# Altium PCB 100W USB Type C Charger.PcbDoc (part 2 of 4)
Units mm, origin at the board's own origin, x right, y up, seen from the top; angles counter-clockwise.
Board outline 79.45 x 55.68 mm, 4 copper layers (Top Layer, Signal Layer 1, Signal Layer 2, Bottom Layer), stack 1.565 mm thick; 161 components, 84 nets, 462 pads, 2175 vias.
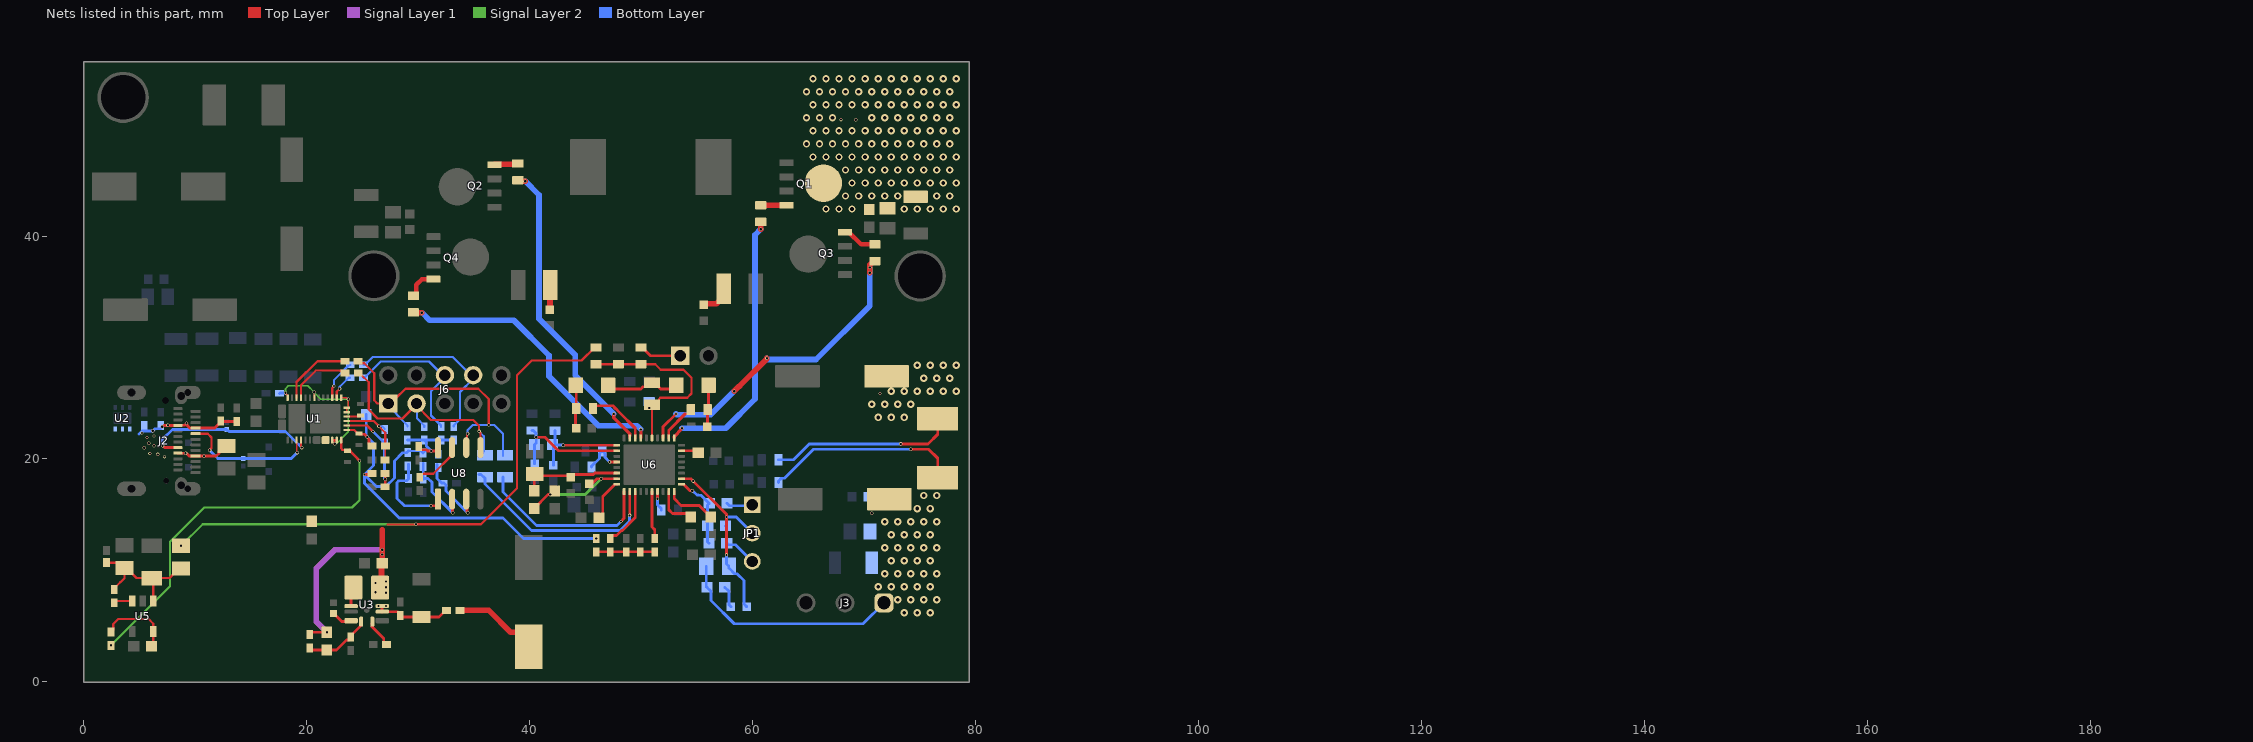
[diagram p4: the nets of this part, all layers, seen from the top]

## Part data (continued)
JP1: library part CMP-0002338-1, "Header, 100mil, 3x1, Tin, TH", Color=Black, Current_A=3A, Manufacturer="Sullins Connector Solutions", Supplier Part Number 1=S1012E-03-ND, Voltage_V=1.8kV
L1: library part CMP-0003375-1, "Ferrite Bead, 21 ohm @ 100 MHz, 6 A, 0805", Manufacturer="Taiyo Yuden", Supplier Part Number 1=587-1765-1-ND, Value1="0.004 ohm", Value2=6A, ValueDisplayed="21 ohm"
L3: library part CMP-0096007-1, "Power Choke Coil 10uH 20% 9A 22mOhm", Manufacturer=Cyntec, Operating Temperature Range="-55°C to +125°C", Test Frequency=100kHz, Tolerance_%=20%
LBL1: library part CMP-0003625-1, "Thermal Transfer Printable Labels, 0.650\" W x 0.200\" H - 10,000 per roll", Manufacturer=Brady, Supplier Part Number 1=97C5133
Logo1: library part CMP-0074838-1, "Texas Instrument Corporate Signature"
Logo3: library part CMP-0074847-1, "FCC_disclaimer"
Q1 Q2 Q3 Q4: library part CMP-0096839-1, "N-Channel 80 V 18.6A (Ta), 70.6A (Tc) 5W (Ta), 71.4W (Tc) Surface Mount PowerPAK® SO-8", Digikey Part Number=742-SIR880BDP-T1-RE3CT-ND, Drain To Source Breakdown Voltage=80V, Input Capacitace At Vds="2930pF @ 40V", Manufacturer=Vishay, Mouser Part Number=78-SIR880BDP-T1-RE3, Operating Temperature Range="-55°C to +150°C", Power_W=5W, Pulse Drain Current=200A, Typ Forward Diode Voltage=0.74V, Value2=SiR122LDP
R1 R6: library part CMP-0026753-1, "RES, 100 k, 1%, 0.063 W, AEC-Q200 Grade 0, 0402", Manufacturer="Stackpole Electronics Inc", Power_W=63mW, Supplier Part Number 1=RMCF0402FT100KCT-ND, TempCo="100 ppm/C", Tolerance_%=1%, Value2=0.063W, Value_Code=100k
R2 R30 R32: library part CMP-0027004-1, "RES, 0, 5%, 0.063 W, 0402", Manufacturer="Yageo America", Power_W=63mW, Supplier Part Number 1=311-0.0JRCT-ND, TempCo="200 ppm/C", Tolerance_%=5%, Value2=0.063W, Value_Code=0000, ValueDisplayed=0
R3 R4 R12 R13: library part CMP-0026918-5, "RES, 3.3 k, 5%, 0.063 W, AEC-Q200 Grade 0, 0402", Manufacturer=Vishay-Dale, Power_W=63mW, Supplier Part Number 1=541-3.3KJCT-ND, TempCo="200 ppm/C", Tolerance_%=5%, Value2=0.063W, Value_Code=3k30, ValueDisplayed=3.3k
R5: library part CMP-0023541-1, "RES, 40.2 k, 0.1%, 0.1 W, 0603", Manufacturer="Susumu Co Ltd", Power_W=100mW, Supplier Part Number 1=RG16P40.2KBCT-ND, TempCo="25 ppm/C", Tolerance_%=0.1%, Value2=0.1W, Value_Code=40k2, ValueDisplayed=40.2k
R7 R14 R15 R22 R23 R24 R74: "RES, 10 k, 5%, 0.063 W, AEC-Q200 Grade 0, 0402", Manufacturer=Vishay-Dale, PartNumber=CRCW040210K0JNED, Power_W=63mW, Supplier Part Number 1=541-10KJCT-ND, TempCo="200 ppm/C", Tolerance_%=5%, Value2=0.063W, Value_Code=10k0, ValueDisplayed=10k
R8 R9 R10 R11 R21 R25 R27 R77: "RES, 0, 5%, 0.063 W, 0402", Manufacturer="Yageo America", PartNumber=RC0402JR-070RL, Power_W=63mW, Supplier Part Number 1=311-0.0JRCT-ND, TempCo="200 ppm/C", Tolerance_%=5%, Value2=0.063W, Value_Code=0000, ValueDisplayed=0
R16 R35 R38 R44 R45 R50 R51 R55 R56 R58 R59 R72: library part CMP-0093629-1, "Thick Film Resistors - SMD 1/10watt ZEROohm Jumper", Manufacturer=Vishay, Operating Temperature Range="-55°C to +155°C", Power=250mW, Power_W=330mW, TempCo=100ppm/°C, Tolerance_%=1%
R17: library part CMP-0026068-2, "RES, 19.6 k, 1%, 0.063 W, 0402", Manufacturer=Vishay-Dale, Power_W=63mW, Supplier Part Number 1=541-19.6KLCT-ND, TempCo="100 ppm/C", Tolerance_%=1%, Value2=0.063W, Value_Code=19k6, ValueDisplayed=19.6k
R18: library part CMP-0026658-1, "RES, 10.0 k, 1%, 0.1 W, 0402", Manufacturer=Panasonic, Power_W=100mW, Supplier Part Number 1=P10.0KLCT-ND, TempCo="100 ppm/C", Tolerance_%=1%, Value2=0.1W, Value_Code=10k0, ValueDisplayed=10.0k
R19: library part CMP-0020817-2, "RES, 3.3, 5%, 0.125 W, 0805", Manufacturer="Yageo America", Power_W=125mW, Supplier Part Number 1=311-3.3ARCT-ND, TempCo="200 ppm/C", Tolerance_%=5%, Value2=0.125W, Value_Code=3R30, ValueDisplayed=3.3
R29 R31: library part CMP-0096841-1, "Res Metal Strip 2512 0.005 Ohm 1% 1W 110ppm/C Molded SMD SMD Embossed Plastic T/R", Digikey Part Number=WSLG-.005CT-ND, Manufacturer=Vishay, Mouser Part Number=71-WSL25125L000FEA, Octopart Part Number=dd8716d1bbbb0240, Operating Temperature Range="-65°C to +170°C", Power_W=1W, TempCo=110ppm/°C, Tolerance_%=1%
R33 R34 R36 R37: library part CMP-0093685-1, "RES Thick Film, 10Ω, 1%, 0.1W, 100ppm/°C, 0603", Approved Alternate Part Number=541-1.00HHCT-ND, Manufacturer=Vishay, Operating Temperature Range="-55°C to +155°C", Power=100mW, TempCo=100ppm/°C, Tolerance_%=1%, Voltage=75V
R39: library part CMP-0024096-3, "RES, 30.1 k, 0.1%, 0.1 W, 0603", Manufacturer="Yageo America", Power_W=100mW, TempCo="25 ppm/C", Tolerance_%=0.1%, Value2=0.1W, Value_Code=30k1, ValueDisplayed=30.1k
R40: library part CMP-0025744-3, "RES, 1.1, 5%, 0.1 W, 0603", Manufacturer=Vishay-Dale, Power_W=100mW, Supplier Part Number 1=541-1.1GCT-ND, TempCo="200 ppm/C", Tolerance_%=5%, Value2=0.1W, Value_Code=1R10, ValueDisplayed=1.1
R41: library part CMP-0018933-2, "Thick Film Resistors - SMD 0805 Anti-Surge Res. 0.1%, 249Kohm", Manufacturer=Panasonic, Power_W=125mW, Supplier Part Number 1=RG20P249KBCT-ND, TempCo="25 ppm/C", Tolerance_%=0.1%, Value2=0.125W, Value_Code=249k
R42 R43: library part CMP-0015022-3, "RES, 3.30, 1%, 0.75 W, AEC-Q200 Grade 0, 1210", Manufacturer=Vishay-Dale, Power_W=750mW, Supplier Part Number 1=541-3.30DCT-ND, TempCo="100 ppm/C", Tolerance_%=1%, Value2=0.75W, Value_Code=3R30, ValueDisplayed=3.30
R46: library part CMP-0021522-3, "Thick Film Resistors - SMD 1/8Watt 1Mohms 1% Commercial Use", Manufacturer="Vishay / Dale", Power_W=125mW, Supplier Part Number 1=P1.00MCCT-ND, TempCo="100 ppm/C", Tolerance_%=1%, Value2=0.125W, Value_Code=1M00, ValueDisplayed=1.00M
R47: library part CMP-0023990-3, "RES, 24.9 k, 0.1%, 0.1 W, 0603", Manufacturer="Yageo America", Power_W=100mW, TempCo="25 ppm/C", Tolerance_%=0.1%, Value2=0.1W, Value_Code=24k9, ValueDisplayed=24.9k
R48: library part CMP-0022977-4, "RES, 294 k, 1%, 0.1 W, 0603", Manufacturer=Yageo, Power_W=100mW, Supplier Part Number 1=311-294KHRCT-ND, TempCo="100 ppm/C", Tolerance_%=1%, Value2=0.1W, Value_Code=294k
R49 R64 R68: library part CMP-0092857-1, "Thick Film Resistors - SMD 1/8watt ZEROohm Jumper", Manufacturer=Vishay, Operating Temperature Range="-55°C to +155°C", Power_W=500mW, TempCo=200ppm/°C, Tolerance_%=5%
R52: library part CMP-0023228-5, "RES, 64.9 k, 1%, 0.1 W, 0603", Manufacturer=Yageo, Power_W=100mW, Supplier Part Number 1=311-64.9KHRCT-ND, TempCo="100 ppm/C", Tolerance_%=1%, Value2=0.1W, Value_Code=64k9, ValueDisplayed=64.9k
R53: library part CMP-0023678-2, "RES, 11.4 k, 0.1%, 0.1 W, 0603", Manufacturer="Yageo America", Power_W=100mW, TempCo="25 ppm/C", Tolerance_%=0.1%, Value2=0.1W, Value_Code=11k4, ValueDisplayed=11.4k
R54: library part CMP-0022990-5, "RES, 2.49 k, 1%, 0.1 W, 0603", Manufacturer=Yageo, Power_W=100mW, Supplier Part Number 1=311-2.49KHRCT-ND, TempCo="100 ppm/C", Tolerance_%=1%, Value2=0.1W, Value_Code=2k49, ValueDisplayed=2.49k
R57: library part CMP-0023199-5, "RES, 5.23 k, 1%, 0.1 W, 0603", Manufacturer=Yageo, Power_W=100mW, Supplier Part Number 1=311-5.23KHRCT-ND, TempCo="100 ppm/C", Tolerance_%=1%, Value2=0.1W, Value_Code=5k23, ValueDisplayed=5.23k
R60: library part CMP-0080485-1, "RES, 10.1 k, 0.1%, 0.1 W, 0603", Manufacturer="TT Electronics/IRC", Power_W=100mW, TempCo="25 ppm/C", Tolerance_%=0.1%, Value2=0.1W, Value_Code=10k1, ValueDisplayed=10.1k
R61: library part CMP-0022371-2, "RES, 3.01 k, 1%, 0.1 W, 0603", Manufacturer=Vishay-Dale, Power_W=100mW, Supplier Part Number 1=541-3.01KHCT-ND, TempCo="100 ppm/C", Tolerance_%=1%, Value2=0.1W, Value_Code=3k01, ValueDisplayed=3.01k
R62: library part CMP-0023018-5, "RES, 30.1 k, 1%, 0.1 W, 0603", Manufacturer=Yageo, Power_W=100mW, Supplier Part Number 1=311-30.1KHRCT-ND, TempCo="100 ppm/C", Tolerance_%=1%, Value2=0.1W, Value_Code=30k1, ValueDisplayed=30.1k
R63: library part CMP-0022735-5, "RES, 100 k, 1%, 0.1 W, 0603", Manufacturer=Yageo, Power_W=100mW, Supplier Part Number 1=311-100KHRCT-ND, TempCo="100 ppm/C", Tolerance_%=1%, Value2=0.1W, Value_Code=100k
R67: library part CMP-0026133-2, "RES, 1.10, 1%, 0.063 W, AEC-Q200 Grade 0, 0402", Manufacturer=Vishay-Dale, Power_W=63mW, Supplier Part Number 1=541-1.10LLCT-ND, TempCo="100 ppm/C", Tolerance_%=1%, Value2=0.063W, Value_Code=1R10, ValueDisplayed=1.10
R69 R70 R71 R73: library part CMP-0078781-1, "RES, 10.5 k, 1%, 0.063 W, 0402", Manufacturer="Yageo America", Power_W=63mW, Supplier Part Number 1=YAG2951CT-ND, TempCo="100 ppm/C", Tolerance_%=1%, Value2=0.063W, Value_Code=10k5, ValueDisplayed=10.5k
R75: library part CMP-0018483-2, "RES, 7.50 k, 1%, 0.25 W, 1206", Manufacturer="Yageo America", Power_W=250mW, Supplier Part Number 1=311-7.50KFRCT-ND, TempCo="100 ppm/C", Tolerance_%=1%, Value2=0.25W, Value_Code=7k50, ValueDisplayed=7.50k
U1: library part CMP-0098263-1, "USB Type-C and USB PD Controller with Integrated Power Switches Optimized for Power Applications", Manufacturer="Texas Instruments", Operating Temperature Range=to
U2: library part CMP-0077834-1, "22-V Precision Surge Protection Clamp, DRV0006A (WSON-6)", Alternate Manufacturer="Texas Instruments"
U3: library part CMP-0097147-1, "3-V to 65-V Input, 1-V to 13-V Output, 600-mA Synchronous Buck Converter Power Module in a HotRod QFN Package", Manufacturer="Texas Instruments", Max Supply Voltage=65V, Min Supply Voltage=3.6V, Nominal Supply Current=17-18uA, Operating Temperature Range="-40°C to +125°C", Output Voltage=1-13V, Switching Frequency=200-2200kHz
U5: library part CMP-0035539-1, "Single Output LDO, 150 mA, Fixed 3.3 V Output, 2.7 to 10 V Input, with Low IQ, 5-pin SOT-23 (DBV), -40 to 125 degC, Green (RoHS & no Sb/Br)", Manufacturer="Texas Instruments"
U6: library part CMP-0093460-1, Alternate Manufacturer=None, Manufacturer="Texas Instruments", Operating Temperature Range=to
U8: library part CMP-0091847-1, "EEPROM Memory IC 512Kb (64K x 8) I²C 1MHz 900ns 8-SOIC", Digikey Part Number=CAT24C512WI-GT3OSCT-ND, Frequency_Fixed=1MHz, Manufacturer="ON Semi", Max Supply Voltage=5.5V, Min Supply Voltage=1.8V, Mouser Part Number=863-CAT24C512WI-GT3, Operating Temperature Range="-40°C to +85°C"
ZZ1: library part CMP-0003616-3
ZZ2: library part CMP-0077236-1
ZZ3: library part CMP-0077237-1
ZZ4: library part CMP-0077238-1

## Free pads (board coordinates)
  round 4.6 hole 4: 2(3.538,52.436) 2(26.037,36.44) 2(75.041,36.42)

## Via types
v1: diameter 0.4, hole 0.2, Top Layer to Bottom Layer, 1357 vias
v2: diameter 0.66, hole 0.33, Top Layer to Bottom Layer, 627 vias
v3: diameter 0.3, hole 0.2, Top Layer to Bottom Layer, tented both sides, 152 vias
v4: diameter 0.5, hole 0.2, Top Layer to Bottom Layer, 18 vias
v5: diameter 0.5, hole 0.2, Top Layer to Bottom Layer, tented both sides, 16 vias
v6: diameter 0.4, hole 0.2, Top Layer to Bottom Layer, tented both sides, 3 vias
v7: diameter 0.35, hole 0.2, Top Layer to Bottom Layer, tented both sides, 2 vias

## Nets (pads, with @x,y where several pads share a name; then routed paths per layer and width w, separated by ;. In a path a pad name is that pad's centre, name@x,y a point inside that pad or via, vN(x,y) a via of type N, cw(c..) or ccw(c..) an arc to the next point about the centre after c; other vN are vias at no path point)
/CE: R58.1 U6.7 | length 1.8
  Top Layer w0.254: v3(51.481,16.428) U6.7@51.481,17.083
  Bottom Layer w0.254: v3@51.481,16.415 51.481,15.877 51.81,15.548 R58.1@51.81,15.423
/INT: R73.1 U6.3 | length 5.4
  Top Layer w0.254: R73.1@47.234,12.867 47.234,12.967 47.407,13.14 47.792,13.14 48.246,13.594 48.341,13.594 49.481,14.735 U6.3@49.481,17.083
/PG: R69.1 U6.6 | length 4.3
  Top Layer w0.254: U6.6@50.981,17.083 50.981,13.896 51.23,13.648 51.23,12.868 R69.1@51.231,12.867
ACN: C27.2 C31.1 R34.1 U6.29 | length 8.8
  Top Layer w0.254: v3(43.016,21.23) 43.019,21.233 U6.29@47.831,21.233
  Bottom Layer w0.254: C31.1@42.14,19.435 42.14,21.183 42.147,21.19 42.153,21.196 C27.2@42.216,21.259 ; R34.1@42.282,22.548 42.282,21.325 C27.2@42.216,21.259 ; v3(43.016,21.23) 43.003,21.23 42.985,21.249 42.227,21.249 C27.2@42.216,21.259
ACOV: C40.1 R48.1 R52.2 U6.35 | length 10.4
  Top Layer w0.254: R48.1@40.423,15.548 40.423,15.573 41.65,16.799 41.865,16.799 41.872,16.793 41.872,16.801 R52.2@41.878,16.808 ; v3(41.857,16.808) R52.2@41.878,16.808 ; R52.2@42.254,17.132 41.93,16.808 R52.2@41.878,16.808 ; C40.1@45.365,17.781 45.391,17.755 45.591,17.755 46.068,18.233 v3(46.423,18.233) U6.35@47.831,18.233 U6.35@47.829,18.231
  Signal Layer 2 w0.254: v3(41.857,16.808) 44.997,16.808 v3(46.423,18.233)
ACP: C27.1 C30.1 R33.1 U6.30 | length 11
  Top Layer w0.254: v3@40.608,21.95 41.38,21.95 42.597,20.733 U6.30@47.831,20.733
  Bottom Layer w0.254: R33.1@40.207,22.561 40.332,22.561 40.58,22.313 40.58,22.161 40.587,22.154 40.587,21.959 v3(40.596,21.95) 40.596,21.442 C27.1@40.452,21.298 C30.1@40.452,19.579
ACUV: C37.1 R46.1 R48.2 U6.34 | length 8.9
  Top Layer w0.254: R48.2@40.423,17.148 40.423,18.292 40.631,18.5 43.528,18.5 C37.1@43.671,18.357 43.925,18.611 45.731,18.611 45.853,18.733 U6.34@47.831,18.733
ADCIN1: R6.2 R25.2 R30.2 U1.2 | length 8.5
  Top Layer w0.2: U1.2@23.594,22.999 25.416,22.999 v3(25.949,22.467) ; R30.2@27.043,17.505 R6.2@27.044,18.692
  Bottom Layer w0.254: v3(25.949,22.467) 26.662,21.754 26.666,21.754 26.994,21.426 26.994,18.248 27.043,18.199 v3(27.043,18.187)
ADCIN2: R1.1 R2.2 R25.1 U1.3 | length 7
  Top Layer w0.152: R2.2@27.044,19.912 R1.1@27.044,21.147
  Top Layer w0.2: U1.3@23.594,23.399 26.009,23.399 27.043,22.365 27.043,21.176 R1.1@27.059,21.16
  Bottom Layer w0.152: v3(26.48,22.928) 26.77,22.928 26.994,22.704 R25.1@26.994,22.627
BAT: C61.1 C62.1 C67.2 C68.1 C69.1 J3.1 R29.2 R37.1 R40.2 R41.2 R77.2 | length 45.8
  Top Layer w0.254: v3(74.188,20.878) 75.796,20.878 76.611,20.063 R29.2@76.611,18.326
  Top Layer w0.5: R77.2@33.756,6.41 36.341,6.41 38.295,4.455 38.929,4.455 39.929,3.455 C62.1@39.929,3.163
  Bottom Layer w0.254: R41.2@55.843,10.381 55.843,8.54 R40.2@55.906,8.476 55.931,8.476 56.279,8.128 56.279,7.297 58.364,5.212 69.919,5.212 J3.1@71.799,7.092 ; R37.1@62.333,17.899 62.333,18.024 62.581,18.272 62.876,18.272 65.482,20.878 v3(74.188,20.878)
  other v2: 73.604,6.203 74.773,6.203 75.941,6.203 73.02,7.371 74.188,7.371 75.357,7.371 76.525,7.371 71.267,8.539 72.436,8.539 73.604,8.539 74.773,8.539 75.941,8.539 71.852,9.708 73.02,9.708 74.188,9.708 75.357,9.708 76.525,9.708 72.436,10.876 73.604,10.876 74.773,10.876 75.941,10.876 71.852,12.045 73.02,12.045 74.188,12.045 75.357,12.045 76.525,12.045 72.436,13.213 73.604,13.213 74.773,13.213 75.941,13.213 71.852,14.381 73.02,14.381 74.188,14.381 75.357,14.381 76.525,14.381 74.773,15.55 75.941,15.55 75.357,16.718 76.525,16.718
  other v3: 70.688,15.141
BTST1: R50.1 U6.26 | length 5.9
  Top Layer w0.254: R50.1@45.534,24.346 45.534,24.471 45.782,24.719 45.907,24.719 45.971,24.783 47.455,24.783 47.732,24.506 47.742,24.506 48.022,24.227 48.022,24.216 49.481,22.756 U6.26@49.481,21.883
BTST2: R51.1 U6.20 | length 3.5
  Top Layer w0.254: U6.20@52.481,21.883 52.481,22.569 53.964,24.052 54.22,24.052 54.468,24.3 R51.1@54.468,24.425
C_CC1: C11.1 J2.A5 U1.28 | length 12.3
  Top Layer w0.152: U1.28@19.094,21.699 19.118,21.675 19.118,20.644 19.149,20.613 v3(19.149,20.573)
  Top Layer w0.2: J2.A5@10.043,22.267 11.119,22.267 11.46,21.926 11.46,20.977 11.293,20.81 v3(11.293,20.782)
  Bottom Layer w0.254: v3(11.293,20.782) 12.031,20.044 C11.1@14.315,20.044 18.621,20.044 v3(19.149,20.573)
C_CC2: C10.1 J2.B5 U1.29 | length 16.2
  Top Layer w0.152: U1.29@19.494,21.699 19.494,21.12 19.556,21.058 v3(19.556,21.018) ; U1.29@19.505,21.699 U1.29@19.505,21.729
  Top Layer w0.254: v3(7.077,21.175) 7.09,21.175 7.248,21.017 J2.B5@8.443,21.017
  Bottom Layer w0.254: v3(7.077,21.175) 7.077,21.775 7.961,22.659 11.637,22.659 11.64,22.656 C10.1@12.693,22.656 ; C10.1@12.819,22.638 12.819,22.618 12.902,22.535 12.977,22.535 13.051,22.461 18.113,22.461 18.861,21.714 v3(19.556,21.018)
DRV_SUP: C42.1 R16.1 R49.2 R55.2 R72.2 U6.23 | length 18.1
  Top Layer w0.2: R72.2@45.961,28.507 R55.2@47.963,28.507 R16.1@49.981,28.507 51.272,28.507 51.771,28.009 53.814,28.009 54.535,27.287 54.535,25.877 54.145,25.487 51.723,25.487 51.606,25.37 51.606,25.25 51.231,24.875 R49.2@50.981,24.875 U6.23@50.981,21.883 ; v3(50.726,24.576) 50.731,24.581 R49.2@50.731,24.849
  Bottom Layer w0.2: v3(50.726,24.576) 50.726,24.894 C42.1@50.731,24.899
EXT_DRV: J4.1 R16.2 | length 4.5
  Top Layer w0.254: R16.2@49.981,30.007 50.106,30.007 50.856,29.257 J4.1@53.512,29.257
  Bottom Layer w0.254: J4.1@53.081,29.689 J4.1@53.512,29.257
FB: C34.2 JP1.2 R41.1 R47.2 U6.12 | length 18.3
  Top Layer w0.254: U6.12@53.631,18.233 54.457,18.233 54.566,18.125 v3(54.674,18.016) ; v3(54.674,18.016) 57.653,15.037 57.653,14.801 v3(57.662,14.792) v3(57.662,11.395)
  Bottom Layer w0.254: R47.2@57.587,13.996 57.662,14.071 v3(57.662,14.792) 58.536,14.792 JP1.2@59.981,13.348 ; v3(57.662,11.395) 57.662,10.594 R41.1@57.875,10.381 57.875,10.216 58.383,9.708 58.616,9.708 59.225,9.099 59.225,6.998 C34.2@59.479,6.744
FBG: R39.1 R47.1 R53.1 U6.11 | length 6.9
  Top Layer w0.254: U6.11@53.631,17.733 53.802,17.733 54.381,17.155 54.594,17.155 v3(54.602,17.146)
  Bottom Layer w0.254: v3(54.602,17.146) 54.611,17.137 54.637,17.137 55.006,16.768 55.135,16.768 55.153,16.75 55.374,16.75 56.027,16.097 56.098,16.026 R39.1@56.123,16.026 55.957,15.86 R47.1@55.957,13.996 ; R47.1@55.987,13.996 R47.1@55.957,13.996 ; R53.1@56.091,12.433 55.957,12.567 R47.1@55.957,13.996
FSW_SYNC: R63.2 U6.36 | length 3.8
  Top Layer w0.254: R63.2@46.217,14.745 R63.2@46.217,14.745 46.567,15.093 46.567,16.64 47.66,17.733 U6.36@47.831,17.733
HIDRV1: R38.2 U6.27 | length 27.6
  Top Layer w0.254: U6.27@48.979,22.064 48.979,21.885 U6.27@48.981,21.883
  Top Layer w0.3: v3(47.545,24.029) 47.545,23.71 48.979,22.276 U6.27@48.979,22.064
  Top Layer w0.508: R38.2@38.942,45.012 39.029,44.925 v3(39.616,44.925)
  Bottom Layer w0.508: v3(39.616,44.925) 40.843,43.698 40.843,32.582 44.09,29.336 44.09,27.484 v3(47.545,24.029)
HIDRV2: R35.2 U6.19 | length 24.9
  Top Layer w0.3: U6.19@52.981,21.883 52.981,22.008 53.672,22.698 v3(53.672,22.757)
  Top Layer w0.5: v3(60.738,40.619) R35.2@60.739,41.267
  Bottom Layer w0.508: v3(53.672,22.757) 57.592,22.757 60.222,25.388 60.222,40.103 v3(60.738,40.619)
I2C_SCL: J6.1 R10.2 R12.2 R68.2 U8.6 | length 28.6
  Top Layer w0.2: R10.2@24.623,28.778 24.808,28.593 25.163,28.593 26.055,27.702 26.055,25.268 26.339,24.983 27.116,24.983 27.263,24.836 J6.1@27.914,25.487 ; J6.1@27.976,25.426 28.858,26.307 35.406,26.307 36.33,25.383 v3(36.33,23.054) ; U8.6@34.317,20.362 34.383,20.428 34.383,22.172 34.438,22.227 v3(34.438,22.254)
  Bottom Layer w0.2: J6.1@27.325,24.774 28.05,24.049 28.05,24.001 29.036,23.014 R12.2@29.036,22.914 ; v3(34.438,22.254) 34.438,22.589 34.903,23.054 v3(36.33,23.054) 36.832,23.054 37.619,22.266 R68.2@37.619,20.276
I2C_SDA: J6.3 R11.2 R13.2 R64.2 U8.5 | length 21.4
  Top Layer w0.2: R11.2@24.629,27.719 24.729,27.719 24.929,27.519 25.564,26.885 25.564,24.429 26.356,23.637 28.604,23.637 J6.3@29.729,24.762 ; J6.3@29.865,24.774 31.135,23.504 34.953,23.504 35.469,22.988 35.469,22.45 35.587,22.331 U8.5@35.587,21.027
  Bottom Layer w0.2: J6.3@29.865,24.774 29.896,24.743 29.896,23.649 30.555,22.991 R13.2@30.555,22.891 ; v3(35.469,22.477) 35.896,22.05 35.896,20.703 35.758,20.565 R64.2@35.705,20.565
I2CS_SCL: J6.8 R3.1 R8.2 | length 16
  Bottom Layer w0.2: R8.2@25.108,28.44 25.208,28.44 25.907,29.139 33.12,29.139 34.945,27.314 34.945,27.189 33.756,26 33.756,23.561 33.197,23.003 R3.1@33.197,22.903
I2CS_SDA: J6.6 R4.1 R9.2 | length 13.8
  Bottom Layer w0.2: R9.2@25.095,27.296 25.195,27.296 26.638,28.739 30.98,28.739 32.405,27.314 31.158,26.067 31.158,23.901 32.061,22.998 R4.1@32.061,22.898
ICHG: R60.2 U6.9 | length 3.9
  Top Layer w0.254: U6.9@52.481,17.083 52.481,15.448 52.833,15.096 54.153,15.096 R60.2@54.453,14.796
ILIM_HIZ: R54.2 U6.10 | length 4.6
  Top Layer w0.254: U6.10@52.981,17.083 52.981,16.444 53.586,15.84 55.218,15.84 56.237,14.821 R54.2@56.237,14.796
LDO_1V5: C9.2 U1.4 | length 1.2
  Top Layer w0.2: U1.4@23.594,23.799 24.755,23.799 C9.2@24.813,23.857
LDO_3V3: C7.2 C8.2 C15.1 R1.2 R3.2 R4.2 R6.1 R7.2 R12.1 R13.1 R14.2 R15.2 R67.1 U1.1 U8.8 | length 50.2
  Top Layer w0.2: U1.1@23.794,22.599 24.266,22.599 24.584,22.281 C8.2@24.698,22.281
  Top Layer w0.254: C8.2@24.698,22.281 24.762,22.217 25.174,22.217 25.586,21.806 25.586,21.333 25.759,21.16 R1.2@25.859,21.16 ; v3(25.193,18.611) 25.202,18.62 25.771,18.62 R6.1@25.844,18.692 ; C15.1@30.064,21.104 30.064,21.004 30.237,20.831 30.745,20.831 30.855,20.722 31.176,20.722 v3(31.184,20.713) 31.643,20.713 31.777,20.847 U8.8@31.777,21.027
  Bottom Layer w0.2: R7.2@29.139,20.731 29.157,20.713 30.25,20.713 R14.2@30.441,20.522 30.632,20.713 v3(31.184,20.713) R15.2@31.698,20.713
  Bottom Layer w0.254: v3@25.181,18.611 25.187,18.605 25.38,18.412 25.38,18.405 26.262,17.523 27.101,17.523 27.878,18.3 27.878,19.827 28.606,20.556 28.966,20.556 29.139,20.729 R7.2@29.139,20.731 ; C7.2@25.34,23.983 25.34,22.091 25.444,21.987 25.444,21.963 25.998,21.409 25.998,19.415 v3(25.193,18.611) 25.185,18.602 25.185,18.344 25.174,18.334 25.174,17.824 28.3,14.698 37.623,14.698 39.454,12.867 v3(45.971,12.867) ; R12.1@29.036,21.714 30.531,21.714 R13.1@30.555,21.691 ; v3(31.184,20.713) 30.728,21.169 30.728,21.518 R13.1@30.555,21.691 ; R3.2@33.197,21.703 33.185,21.691 32.061,21.691 R13.1@30.555,21.691
  other v3: 25.444,21.975
LODRV1: R44.1 U6.25 | length 26.6
  Top Layer w0.254: U6.25@49.981,21.883 v3(49.981,22.654)
  Top Layer w0.508: R44.1@29.582,33.153 29.608,33.127 v3(30.333,33.127)
  Bottom Layer w0.5: 46.155,22.998 49.638,22.998 v3(49.981,22.654)
  Bottom Layer w0.508: v3(30.333,33.127) 31.016,32.443 38.585,32.443 41.737,29.292 41.737,27.416 46.155,22.998
LODRV2: R45.1 U6.21 | length 29
  Top Layer w0.254: U6.21@51.981,21.883 51.981,22.887 v3(53.131,24.037)
  Top Layer w0.5: v3(70.513,36.709) v3(70.513,37.174)
  Top Layer w0.508: v3(58.354,26.08) 58.813,26.539 58.841,26.539 61.29,28.988 v3(61.29,29.029) ; v3(70.513,37.174) 70.513,37.414 70.85,37.752 R45.1@70.975,37.752
  Bottom Layer w0.508: v3(53.131,24.037) 53.201,23.967 56.244,23.967 58.354,26.078 v3(58.354,26.08) ; v3(61.29,29.029) 61.4,28.919 65.697,28.919 70.513,33.735 v3(70.513,36.709) v3(70.513,37.174)
MODE: R61.2 U6.17 | length 1.6
  Top Layer w0.254: U6.17@53.631,20.733 54.944,20.733 R61.2@55.136,20.541
NetC3_1: C3.1 C4.1 C5.1 C6.1 J2.A4 J2.A9 J2.B4 J2.B9 L1.1 U2.4 U2.5 U2.6 | length 14.7
  Top Layer w0.254: v3(7.045,22.887) 7.058,22.887 7.188,23.017 v3(7.55,23.017) J2.B9@8.443,23.017 8.451,23.025 9.041,23.025 9.212,23.197 v3(9.224,23.197) 9.224,23.184 9.266,23.142 9.266,23.026 9.517,22.775 10.035,22.775 J2.A4@10.043,22.767 11.758,22.767 12.285,23.295 C5.1@12.285,23.395 12.32,23.36 C6.1@13.733,23.36 ; J2.B4@8.443,20.517 8.448,20.513 9.137,20.513 9.15,20.499 9.242,20.499 9.466,20.275 10.035,20.275 10.05,20.261 10.783,20.261 v3(10.789,20.255) 10.79,20.256 11.876,20.256 12.125,20.505 12.125,20.67 12.633,21.178 L1.1@12.799,21.178
  Bottom Layer w0.254: 4.952,22.233 5.243,22.524 6.206,22.524 6.401,22.718 6.876,22.718 v3(7.045,22.887)
  other v3: 7.246,20.212 6.637,20.413 5.935,20.493 9.141,20.508 5.428,21.007 6.301,21.19 5.837,21.414 5.68,21.93 6.301,22.067 5.219,22.329 6.194,22.524
NetC16_1: C16.1 C17.1 R77.1 U3.2 U3.3 | length 6.8
  Top Layer w0.254: U3.2@26.772,6.284 U3.2@26.79,6.302 ; 26.772,6.622 26.772,6.32 U3.2@26.79,6.302 ; C17.1@28.241,6.122 C17.1@28.387,5.976 ; R77.1@32.556,6.41 32.456,6.41 31.865,5.818 C16.1@30.289,5.818 28.545,5.818 C17.1@28.387,5.976 ; U3.2@26.79,6.302 28.162,6.302 28.387,6.076 C17.1@28.387,5.976
  other v7: 26.44,6.802 27.12,6.802
NetC18_1: C18.1 U3.8 | length 1.9
  Top Layer w0.254: C18.1@22.404,6.142 22.429,6.142 23.151,5.421 23.921,5.421 U3.8@23.99,5.49
NetC19_2: C19.2 R5.1 R18.2 U3.9 | length 5.8
  Top Layer w0.254: C19.2@20.288,3.051 20.288,3.03 20.461,2.857 22.675,2.857 23.564,3.747 23.771,3.747 23.944,3.92 R18.2@23.944,4.02 ; R18.2@23.944,4.12 24.842,5.017 24.842,5.192 U3.9@24.872,5.222
NetC24_1: C24.1 D3.1 R19.1 R27.2 R75.1 U5.1 | length 12.1
  Top Layer w0.2: D3.1@2.04,10.699 3.025,10.699 3.491,10.233 C24.1@3.656,10.233 ; R27.2@2.725,8.298 2.725,8.398 3.276,8.948 3.306,8.948 3.656,9.298 C24.1@3.656,10.233 ; U5.1@6.241,7.264 6.241,9.165 R75.1@6.091,9.315 ; R19.1@8.724,10.184 8.559,10.184 7.69,9.315 R75.1@6.091,9.315 ; C24.1@3.656,10.233 3.821,10.233 4.739,9.315 R75.1@6.091,9.315
NetC25_1: C25.1 R21.2 U5.5 | length 6.8
  Top Layer w0.2: R21.2@2.454,4.481 2.654,4.681 2.654,5.201 3.092,5.639 5.826,5.639 6.241,5.225 6.241,3.366 C25.1@6.091,3.216
NetC34_1: C34.1 R40.1 | length 2
  Bottom Layer w0.254: R40.1@57.506,8.476 57.531,8.476 57.879,8.128 57.879,6.921 C34.1@58.057,6.744
NetC35_1: C35.1 R42.1 | length 3.2
  Top Layer w0.508: R42.1@41.558,36.462 41.558,35.762 R42.1@41.793,35.527 ; C35.1@41.813,33.41 41.838,33.435 41.838,35.572 R42.1@41.863,35.597
NetC36_1: C36.1 R43.1 | length 2.8
  Top Layer w0.508: C36.1@55.623,33.827 55.727,33.931 56.766,33.931 57.403,34.568 R43.1@57.403,35.268
NetC38_2: C38.2 D4.1 R50.2 | length 3.7
  Top Layer w0.254: R50.2@44.127,24.346 44.127,22.815 C38.2@44.166,22.776 ; D4.1@44.138,26.612 44.183,26.567 R50.2@44.183,24.517
NetC39_1: C39.1 D5.1 R51.2 | length 3.8
  Top Layer w0.254: C39.1@55.929,22.886 55.968,22.925 R51.2@55.968,24.425 56.052,24.51 D5.1@56.052,26.612
NetD4_2: D4.2 D5.2 R49.1 | length 6.8
  Top Layer w0.254: D4.2@47.038,26.612 47.365,26.285 49.998,26.285 50.189,26.477 50.883,26.477 51.231,26.825 51.771,26.285 52.825,26.285 D5.2@53.152,26.612
NetJP1_1: JP1.1 R39.2 | length 2.4
  Bottom Layer w0.254: R39.2@57.723,16.026 57.948,15.801 59.894,15.801 JP1.1@59.981,15.888
NetJP1_3: JP1.3 R53.2 | length 3
  Bottom Layer w0.254: R53.2@57.691,12.433 57.813,12.311 58.477,12.311 JP1.3@59.981,10.808
NetQ1_4: Q1.4 R35.1 | length 2.3
  Top Layer w0.508: R35.1@60.739,42.767 Q1.4@63.05,42.767
NetQ2_4: Q2.4 R38.1 | length 2.2
  Top Layer w0.508: Q2.4@36.838,46.397 36.888,46.448 38.878,46.448 R38.1@38.942,46.512
NetQ3_4: Q3.4 R45.2 | length 3.1
  Top Layer w0.4: Q3.4@68.638,40.349 69.736,39.252 R45.2@70.975,39.252
  Top Layer w0.508: Q3.4@68.308,40.349 Q3.4@68.638,40.349
NetQ4_4: Q4.4 R44.2 | length 2.6
  Top Layer w0.4: R44.2@29.582,34.653 29.658,34.653 29.833,34.828 29.833,35.628 30.343,36.138 Q4.4@31.063,36.138
NetR7_1: R7.1 R23.2 U8.1 | length 8.4
  Top Layer w0.254: v3(31.158,15.801) 31.632,15.801 31.777,15.946 U8.1@31.777,16.395
  Bottom Layer w0.254: R7.1@29.139,19.531 R23.2@29.139,18.247 29.139,18.215 28.966,18.042 28.262,18.042 28.114,17.894 28.114,16.457 28.77,15.801 v3(31.158,15.801)
NetR8_1: R8.1 U1.9 | length 3.7
  Top Layer w0.2: U1.9@22.294,25.499 22.294,26.376 22.442,26.523 v3(22.442,26.55)
  Bottom Layer w0.2: v3(22.442,26.55) 22.442,27.074 23.808,28.44 R8.1@23.908,28.44
NetR9_1: R9.1 U1.8 | length 2.4
  Top Layer w0.2: U1.8@22.694,25.499 22.694,26.045 v3(22.956,26.307)
  Bottom Layer w0.2: v3(22.956,26.307) 22.975,26.326 22.975,26.477 23.595,27.096 23.795,27.296 R9.1@23.895,27.296
NetR10_1: R10.1 U1.17 | length 6.3
  Top Layer w0.2: U1.17@19.094,25.499 19.094,26.907 20.965,28.778 R10.1@23.247,28.778
NetR11_1: R11.1 U1.16 | length 5.7
  Top Layer w0.2: U1.16@19.494,25.499 19.494,26.61 20.812,27.927 23.012,27.927 23.02,27.919 23.229,27.919 R11.1@23.429,27.719
NetR14_1: R14.1 R24.2 U8.2 | length 7.1
  Top Layer w0.254: U8.2@33.047,16.395 33.095,16.347 33.095,15.184 v3(33.104,15.175)
  Bottom Layer w0.254: R14.1@30.453,19.598 R24.2@30.453,18.182 30.529,18.258 30.884,18.258 31.232,17.91 31.232,17.046 v3(33.104,15.175)
NetR15_1: R15.1 R74.2 U8.3 | length 6.8
  Top Layer w0.254: U8.3@34.317,16.395 34.373,16.339 34.373,15.256 34.442,15.188 v3(34.442,15.175)
  Bottom Layer w0.254: R15.1@31.707,19.497 31.707,18.25 32.124,17.832 32.324,17.832 32.497,17.659 32.497,17.12 v3(34.442,15.175)
NetR17_2: R17.2 U3.11 | length 2.5
  Top Layer w0.254: 25.872,4.947 25.92,4.899 ; U3.11@25.872,5.222 25.92,5.174 25.92,4.899 ; R17.2@27.177,3.357 27.084,3.357 26.911,3.53 26.911,3.908 25.92,4.899
NetR22_2: R22.2 U8.7 | length 5.2
  Top Layer w0.152: R22.2@29.997,18.315 R22.2@30.097,18.415 ; U8.7@33.047,21.027 U8.7@33.047,21.665
  Top Layer w0.2: R22.2@30.153,18.359 30.153,18.459 30.353,18.659 30.453,18.659 30.477,18.683 31.368,18.683 33.047,20.362 U8.7@33.047,21.027
NetR27_1: R27.1 U5.3 | length 1.7
  Top Layer w0.2: R27.1@2.725,7.098 2.892,7.264 U5.3@4.341,7.264
NetR32_1: R32.1 U1.5 U1.6 U1.7 U1.13 U1.19 U1.36 U1.37 | length 16
  Top Layer w0.152: v3(18.105,25.94) 18.133,25.912 18.133,25.86 18.294,25.699 U1.19@18.294,25.499 ; v3(20.679,25.995) 20.687,25.988 20.687,25.507 U1.13@20.694,25.499 ; U1.36@22.294,21.699 22.494,21.699 22.496,21.697 22.496,21.397 v3(22.52,21.373) ; 22.496,21.699 U1.37@22.694,21.699 ; U1.7@23.094,25.499 23.567,25.499 23.704,25.362 v3(23.744,25.362) 23.744,24.623 23.72,24.599 23.618,24.599 23.594,24.575 U1.5@23.594,24.199
  Signal Layer 2 w0.152: v3(18.105,25.94) 18.105,26.312 18.357,26.563 20.111,26.563 20.659,26.015 20.659,25.975 21.273,25.362 v3(23.744,25.362) 23.744,22.429 22.717,21.401 22.548,21.401 v3(22.52,21.373)
  Bottom Layer w0.152: R32.1@17.729,25.887 R32.1@17.559,25.887 17.6,25.845 17.729,25.845 R32.1@17.823,25.94
  Bottom Layer w0.254: R32.1@17.559,25.887 17.603,25.931 18.096,25.931 v3(18.105,25.94)
NetR56_2: R56.2 R59.2 U6.32 | length 3.8
  Top Layer w0.254: v3(47.181,19.733) U6.32@47.831,19.733
  Bottom Layer w0.254: R56.2@45.553,19.272 45.553,19.349 46.261,20.057 46.269,20.057 46.269,20.477 R59.2@46.517,20.725 46.765,20.477 46.765,20.149 v3@47.172,19.742
NetR64_1: R64.1 U6.2 | length 18.9
  Top Layer w0.254: v3(48.974,14.94) 48.974,14.953 48.989,14.967 48.989,16.735 48.983,16.74 48.983,17.081 U6.2@48.981,17.083
  Bottom Layer w0.254: R64.1@35.455,18.615 35.652,18.615 36,18.267 36,17.759 40.187,13.572 48.129,13.572 48.974,14.417 v3(48.974,14.94)
NetR67_2: R67.2 R69.2 R70.2 R71.2 R73.2 | length 5.3
  Top Layer w0.2: R67.2@45.971,11.667 R73.2@47.234,11.667 R70.2@48.681,11.667 R71.2@49.931,11.667 R69.2@51.231,11.667
NetR68_1: R68.1 U6.1 | length 16.1
  Top Layer w0.254: v3(48.205,14.389) 48.205,14.401 48.481,14.677 U6.1@48.481,17.083
  Bottom Layer w0.254: R68.1@37.623,18.383 37.623,17.037 40.633,14.026 47.843,14.026 v3(48.205,14.389)
NetU3_5: U3.5 U3.6 | length 1.8
  Top Layer w0.254: U3.6@23.974,6.786 23.992,6.804 23.992,8.254 U3.5@24.19,8.452
P3V3: C1.1 R21.1 U1.38 | length 36.5
  Top Layer w0.2: U1.38@23.094,21.699 23.094,20.931 23.211,20.814 23.595,20.814 C1.1@23.663,20.746
  Top Layer w0.254: v3(24.743,19.835) 24.743,19.847 24.375,20.215 24.375,20.224 23.938,20.661 C1.1@23.938,20.718 ; C1.1@23.938,20.718 23.938,20.727 23.848,20.817 23.848,20.808 C1.1@23.938,20.718
  Signal Layer 2 w0.2: v3(2.454,3.281) 7.748,8.576 7.748,12.581 10.807,15.64 24.076,15.64 24.743,16.308 v3(24.743,19.835)
P5V0: C19.1 C21.1 C22.1 R5.2 R19.2 R72.1 U1.34 U1.35 U3.4 | length 73.3
  Top Layer w0.2: R19.2@8.237,12.197 R19.2@8.31,12.27 ; 27.241,14.127 29.792,14.127 v3(29.811,14.146) 35.648,14.146 38.878,17.376 38.878,27.52 40.186,28.829 44.658,28.829 45.836,30.007 R72.1@45.961,30.007
  Top Layer w0.254: C19.1@20.288,4.251 20.288,4.284 20.461,4.457 v3(21.819,4.457)
  Top Layer w0.5: v5(26.17,8.862) U3.4@26.402,8.862 ; U3.4@26.59,8.452 26.59,8.924 26.402,9.112 26.717,9.428 26.717,10.588 C22.1@26.782,10.653 v3(26.782,11.856) 26.782,13.669
  Signal Layer 1 w0.5: v3(21.819,4.457) 20.877,5.398 20.877,10.2 22.534,11.856 v3(26.782,11.856)
  Signal Layer 2 w0.2: v3(8.735,12.206) 10.675,14.146 v3(29.811,14.146)
  other v3: 26.782,11.431
  other v5: 27.12,8.002 26.17,8.042 27.12,8.502 27.12,9.002
P_OUT: C51.2 C53.2 C54.1 C56.1 Q1.5-6-7-8 R29.1 R36.1 | length 16.6
  Top Layer w0.254: v3(73.308,21.355) 75.752,21.355 76.611,22.215 R29.1@76.611,23.616
  Bottom Layer w0.254: R36.1@62.333,19.931 63.677,19.931 65.094,21.349 73.302,21.349 v3(73.308,21.355)
  other v2: 71.267,23.729 72.436,23.729 73.604,23.729 70.683,24.897 71.852,24.897 73.02,24.897 74.188,24.897 72.436,26.065 73.604,26.065 74.773,26.065 75.941,26.065 77.109,26.065 78.278,26.065 75.357,27.234 76.525,27.234 77.694,27.234 74.773,28.402 75.941,28.402 77.109,28.402 78.278,28.402 66.594,42.423 67.762,42.423 68.931,42.423 73.604,42.423 74.773,42.423 75.941,42.423 77.109,42.423 78.278,42.423 68.346,43.591 69.515,43.591 70.683,43.591 71.852,43.591 73.02,43.591 76.525,43.591 77.694,43.591 68.931,44.76 70.099,44.76 71.267,44.76 72.436,44.76 73.604,44.76 74.773,44.76 75.941,44.76 77.109,44.76 78.278,44.76 68.346,45.928 69.515,45.928 70.683,45.928 71.852,45.928 73.02,45.928 74.188,45.928 75.357,45.928 76.525,45.928 77.694,45.928 65.425,47.097 66.594,47.097 67.762,47.097 68.931,47.097 70.099,47.097 71.267,47.097 72.436,47.097 73.604,47.097 74.773,47.097 75.941,47.097 77.109,47.097 78.278,47.097 64.841,48.265 66.01,48.265 67.178,48.265 68.346,48.265 69.515,48.265 70.683,48.265 71.852,48.265 73.02,48.265 74.188,48.265 75.357,48.265 76.525,48.265 77.694,48.265 65.425,49.433 66.594,49.433 67.762,49.433 68.931,49.433 70.099,49.433 71.267,49.433 72.436,49.433 73.604,49.433 74.773,49.433 75.941,49.433 77.109,49.433 78.278,49.433 64.841,50.602 66.01,50.602 67.178,50.602 70.683,50.602 71.852,50.602 73.02,50.602 74.188,50.602 75.357,50.602 76.525,50.602 77.694,50.602 65.425,51.77 66.594,51.77 67.762,51.77 68.931,51.77 70.099,51.77 71.267,51.77 72.436,51.77 73.604,51.77 74.773,51.77 75.941,51.77 77.109,51.77 78.278,51.77 64.841,52.939 66.01,52.939 67.178,52.939 68.346,52.939 69.515,52.939 70.683,52.939 71.852,52.939 73.02,52.939 74.188,52.939 75.357,52.939 76.525,52.939 77.694,52.939 65.425,54.107 66.594,54.107 67.762,54.107 68.931,54.107 70.099,54.107 71.267,54.107 72.436,54.107 73.604,54.107 74.773,54.107 75.941,54.107 77.109,54.107 78.278,54.107
  other v3: 71.443,25.877 67.94,50.446 69.26,50.441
